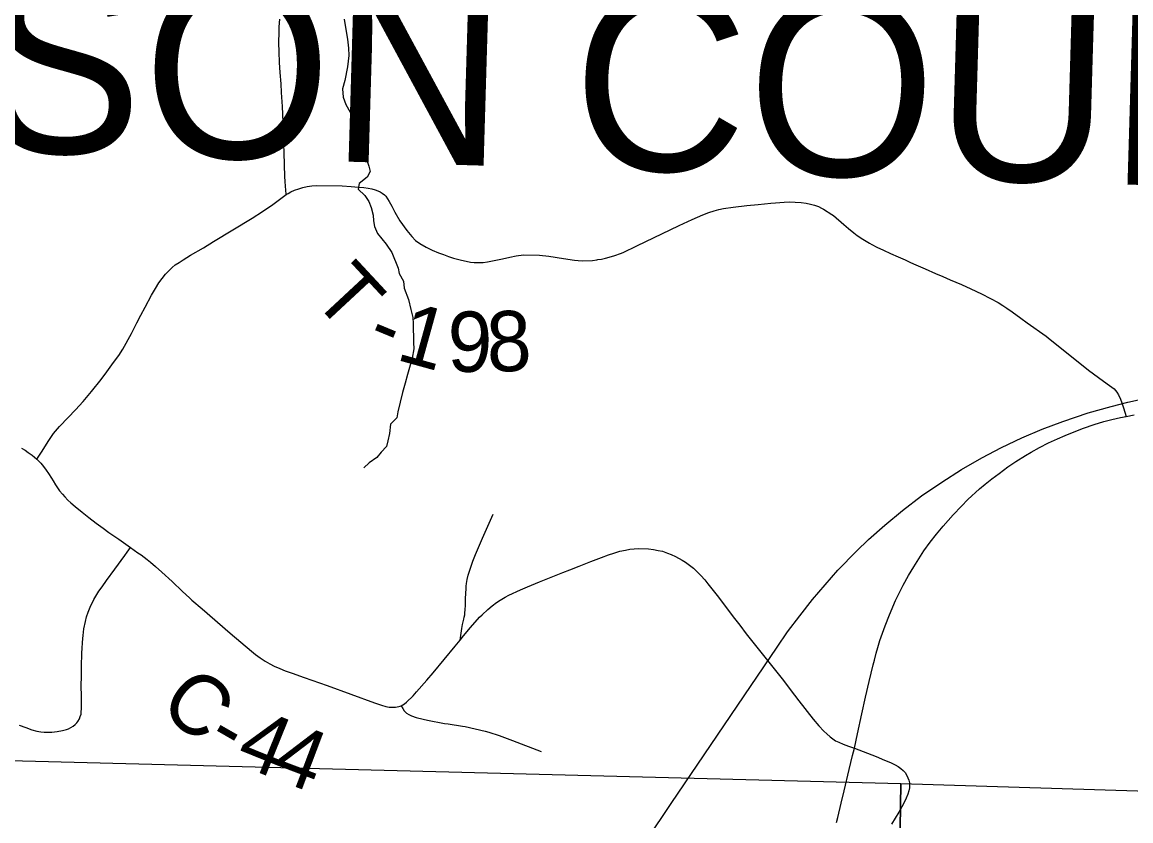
# Model space of a CAD drawing. Extents: x -19.9 to 41.9, y 0 to 32.3.
# Drawn here: x 3.184 to 4.229, y 16.837 to 17.59 of the extents above; entities that cross this region are included whole.
import ezdxf

# ---------------------------------------------------------------- set-up
doc = ezdxf.new("R2010")
doc.units = 0
for name, color, linetype in [('GM_X_Corporation', 7, 'Continuous'), ('GM_X_County_Road', 7, 'Continuous'), ('GM_X_County_Road_Text', 7, 'Continuous'), ('GM_X_County_Text', 7, 'Continuous'), ('GM_X_Minor_River', 7, 'Continuous'), ('GM_X_Rail_Line', 7, 'Continuous'), ('GM_X_State_Route', 7, 'Continuous'), ('GM_X_Township_Road', 7, 'Continuous'), ('GM_X_Township_Road_Text', 7, 'Continuous')]:
    doc.layers.add(name, color=color, linetype=linetype)

msp = doc.modelspace()

# ---------------------------------------------------------------- linework, layer by layer
at = {"layer": 'GM_X_Corporation'}
for points in [[(3.0015, 16.8981), (4.0122, 16.8721), (3.9969, 15.8607), (2.9854, 15.8784)], [(5.0159, 16.8409), (5.0026, 15.928), (5.0009, 15.8404), (3.9969, 15.8607), (4.0122, 16.8721)]]:
    msp.add_lwpolyline(points, close=True, dxfattribs=at)
at = {"layer": 'GM_X_County_Road'}
for points in [[(3.1832, 17.1883), (3.1868, 17.1862), (3.1897, 17.1842), (3.1935, 17.1815), (3.1955, 17.1798), (3.1977, 17.1777), (3.1994, 17.1762), (3.2014, 17.174), (3.204, 17.171), (3.2065, 17.1676), (3.2088, 17.1642), (3.2116, 17.1599), (3.2132, 17.1573), (3.2154, 17.1538), (3.2173, 17.1509), (3.2192, 17.1481), (3.222, 17.1448), (3.2241, 17.1424), (3.227, 17.1393), (3.2299, 17.1366), (3.2339, 17.1332), (3.2405, 17.1278), (3.2467, 17.1229), (3.2538, 17.1175), (3.2603, 17.1127), (3.2657, 17.1088), (3.2749, 17.1024), (3.2859, 17.0947), (3.2931, 17.0897), (3.296, 17.0877), (3.2988, 17.0855), (3.3018, 17.0832), (3.3049, 17.0807), (3.3096, 17.0766), (3.3155, 17.0713), (3.3253, 17.0625), (3.335, 17.0532), (3.3416, 17.0472), (3.3438, 17.0451), (3.3535, 17.0369), (3.3801, 17.014), (3.4, 16.9969), (3.4038, 16.9938), (3.4082, 16.9907), (3.413, 16.9876), (3.4174, 16.985), (3.4216, 16.9828), (3.4268, 16.9805), (3.4318, 16.9785), (3.4384, 16.9762), (3.4497, 16.9722), (3.4715, 16.9646), (3.5159, 16.9483), (3.5226, 16.946), (3.5268, 16.9448), (3.5299, 16.9442), (3.5323, 16.9441), (3.5358, 16.9442), (3.5388, 16.9447), (3.5403, 16.9451), (3.5413, 16.9455)], [(3.5413, 16.9455), (3.5427, 16.9462), (3.5444, 16.9474), (3.5461, 16.9487), (3.5523, 16.9548), (3.5557, 16.9585), (3.5653, 16.9694), (3.5713, 16.9766), (3.5919, 17.0017), (3.5966, 17.0073), (3.5998, 17.0112), (3.6066, 17.0191), (3.6151, 17.0288), (3.6174, 17.0312), (3.6228, 17.0361), (3.6268, 17.0396), (3.631, 17.0428), (3.6344, 17.045), (3.6391, 17.0477), (3.6427, 17.0496), (3.6535, 17.0547), (3.6602, 17.0576), (3.6714, 17.0621), (3.6841, 17.0672), (3.6936, 17.071), (3.7002, 17.0737), (3.7088, 17.0771), (3.7198, 17.0815), (3.7299, 17.0853), (3.7365, 17.0877), (3.7415, 17.0894), (3.7471, 17.091), (3.7525, 17.0922), (3.7566, 17.0929), (3.7608, 17.0934), (3.7647, 17.0936), (3.7743, 17.0933), (3.779, 17.0928), (3.7834, 17.0919), (3.7873, 17.091), (3.7922, 17.0894), (3.7957, 17.088), (3.7996, 17.0862), (3.8061, 17.0827), (3.8091, 17.0809), (3.8129, 17.0781), (3.8166, 17.075), (3.8198, 17.0719), (3.8235, 17.0681), (3.8272, 17.064), (3.8301, 17.0605), (3.8401, 17.0478), (3.8476, 17.0379), (3.8554, 17.0278), (3.8602, 17.0213), (3.8663, 17.0132), (3.9014, 16.9691), (3.9077, 16.9608), (3.9159, 16.9502), (3.9296, 16.9327), (3.9349, 16.9264), (3.9394, 16.9216), (3.9422, 16.9189), (3.9455, 16.916), (3.9479, 16.9143), (3.9506, 16.9125), (3.9535, 16.911), (3.9576, 16.9093), (3.9626, 16.9075), (3.9683, 16.9054)], [(3.5413, 16.9455), (3.5428, 16.9427), (3.544, 16.9408), (3.5448, 16.9398), (3.5461, 16.9386), (3.5483, 16.9372), (3.5509, 16.936), (3.5553, 16.9345), (3.5619, 16.9327), (3.566, 16.9318), (3.582, 16.9288), (3.5854, 16.9284), (3.5989, 16.9263), (3.6015, 16.9258), (3.6202, 16.9216), (3.6237, 16.9206), (3.6336, 16.9173), (3.6461, 16.9128), (3.6732, 16.9024)], [(3.9683, 16.9054), (3.9807, 16.9007), (3.9889, 16.8976), (3.9967, 16.8943), (4.0022, 16.8919), (4.0066, 16.8899), (4.0097, 16.8881), (4.0122, 16.8863), (4.0144, 16.8844), (4.016, 16.8825), (4.0174, 16.8804), (4.0188, 16.8776), (4.0195, 16.8752), (4.0201, 16.8729), (4.0201, 16.8715), (4.0201, 16.868), (4.0196, 16.8652), (4.0187, 16.8621), (4.017, 16.8583), (4.0151, 16.8543), (4.0129, 16.8501), (4.0101, 16.8452), (4.0034, 16.8338)]]:
    msp.add_lwpolyline(points, dxfattribs=at)
at = {"layer": 'GM_X_Minor_River'}
msp.add_lwpolyline([(3.4874, 17.5926), (3.4886, 17.5846), (3.4907, 17.5736), (3.4916, 17.5652), (3.4917, 17.5583), (3.4907, 17.5477), (3.4882, 17.5347), (3.486, 17.527), (3.4865, 17.519), (3.4889, 17.5122), (3.4932, 17.505), (3.4975, 17.496), (3.5026, 17.4831), (3.5061, 17.4729), (3.5082, 17.4619), (3.5106, 17.4539), (3.5118, 17.449), (3.5092, 17.4436), (3.5017, 17.4378), (3.5006, 17.4324), (3.5068, 17.4264), (3.5107, 17.4208), (3.513, 17.4151), (3.5146, 17.4079), (3.5151, 17.4025), (3.5159, 17.3972), (3.5187, 17.3904), (3.5271, 17.3806), (3.5322, 17.3727), (3.5384, 17.358), (3.5393, 17.353), (3.5432, 17.3455), (3.544, 17.339), (3.5479, 17.3284), (3.5504, 17.3189), (3.552, 17.3113), (3.5524, 17.3056), (3.5527, 17.2877), (3.5531, 17.282), (3.5514, 17.2732), (3.5489, 17.2644), (3.5471, 17.2576), (3.5449, 17.2495), (3.5424, 17.2407), (3.5381, 17.2224), (3.537, 17.2167), (3.5311, 17.2109), (3.5301, 17.2021), (3.5286, 17.1952), (3.5272, 17.1898), (3.5224, 17.1844), (3.5183, 17.1794), (3.5111, 17.1744), (3.5059, 17.1697)], dxfattribs=at)
at = {"layer": 'GM_X_Rail_Line'}
msp.add_lwpolyline([(3.7281, 16.7526), (3.7957, 16.8533), (3.8955, 17.0007), (3.9054, 17.0151), (3.9168, 17.0301), (3.9289, 17.0457), (3.9526, 17.0733), (3.9703, 17.0912), (3.9817, 17.1022), (3.9971, 17.1157), (4.0137, 17.1296), (4.0316, 17.1432), (4.0506, 17.1562), (4.0694, 17.1682), (4.0884, 17.179), (4.107, 17.1887), (4.1262, 17.1979), (4.1453, 17.206), (4.1648, 17.2134), (4.1887, 17.2214), (4.2102, 17.2275), (4.2259, 17.2316), (4.2444, 17.2356)], dxfattribs=at)
at = {"layer": 'GM_X_State_Route'}
msp.add_lwpolyline([(3.9513, 16.8354), (3.9526, 16.8402), (3.9559, 16.8536), (3.9587, 16.8653), (3.9635, 16.8855), (3.9666, 16.8984), (3.9683, 16.9054), (3.9712, 16.9189), (3.9752, 16.9377), (3.9789, 16.9536), (3.9822, 16.9682), (3.986, 16.9841), (3.9871, 16.9885), (3.9889, 16.995), (3.9904, 17.0003), (3.9924, 17.0069), (3.9947, 17.0137), (3.9973, 17.0209), (4.0013, 17.0311), (4.0071, 17.0446), (4.0143, 17.059), (4.0194, 17.0681), (4.0244, 17.0763), (4.0291, 17.084), (4.0339, 17.0916), (4.0397, 17.0996), (4.0458, 17.1073), (4.052, 17.1147), (4.0613, 17.1254), (4.0691, 17.1334), (4.0752, 17.1397), (4.0862, 17.1498), (4.0915, 17.1542), (4.0979, 17.1593), (4.1047, 17.1644), (4.1129, 17.1705), (4.1206, 17.1758), (4.1296, 17.1813), (4.1348, 17.1844), (4.1429, 17.1889), (4.1512, 17.1931), (4.1597, 17.1971), (4.1669, 17.2003), (4.1771, 17.2044), (4.1842, 17.207), (4.1943, 17.2104), (4.2034, 17.2132), (4.211, 17.2152), (4.2192, 17.2171), (4.2245, 17.2182), (4.2319, 17.2197)], dxfattribs=at)
at = {"layer": 'GM_X_Township_Road'}
for points in [[(3.4328, 17.4273), (3.4323, 17.4317), (3.4321, 17.4349), (3.4318, 17.4399), (3.4316, 17.4441), (3.4308, 17.4668), (3.4304, 17.4821), (3.4298, 17.4954), (3.4292, 17.5103), (3.4284, 17.5236), (3.4279, 17.5315), (3.4272, 17.5422), (3.4266, 17.5517), (3.4261, 17.5617), (3.4259, 17.5702), (3.4261, 17.5806), (3.4263, 17.5853), (3.4269, 17.5926)], [(3.1977, 17.1777), (3.1997, 17.1808), (3.2028, 17.1855), (3.2083, 17.1944), (3.2135, 17.2021), (3.219, 17.2086), (3.2272, 17.217), (3.2343, 17.2244), (3.2413, 17.2322), (3.2492, 17.2415), (3.2583, 17.253), (3.2638, 17.2601), (3.2699, 17.2689), (3.2749, 17.2755), (3.2789, 17.2814), (3.2869, 17.2964), (3.2921, 17.3064), (3.2959, 17.3137), (3.2998, 17.321), (3.3057, 17.3324), (3.3095, 17.3387), (3.3129, 17.344), (3.3159, 17.3482), (3.3191, 17.3522), (3.3221, 17.3555), (3.3254, 17.3586), (3.3283, 17.3609), (3.3318, 17.3633), (3.3356, 17.3656), (3.3426, 17.37), (3.3548, 17.3772), (3.3644, 17.3829), (3.4006, 17.4049), (3.4104, 17.4114), (3.4203, 17.418), (3.4328, 17.4273), (3.4345, 17.4283), (3.4373, 17.4298), (3.4407, 17.4313), (3.4447, 17.4328), (3.4486, 17.4339), (3.4526, 17.4347), (3.4569, 17.4354), (3.4612, 17.4357), (3.4856, 17.4355), (3.4939, 17.4348), (3.5009, 17.4342), (3.5061, 17.4338), (3.5102, 17.4332), (3.5134, 17.4326), (3.5166, 17.4318), (3.5191, 17.4308), (3.5214, 17.4297), (3.5233, 17.4285), (3.5253, 17.4269), (3.5267, 17.4256), (3.5299, 17.4208), (3.5323, 17.4163), (3.5353, 17.4108), (3.5399, 17.4025), (3.5465, 17.3933), (3.5513, 17.3877), (3.5548, 17.3839), (3.5587, 17.3811), (3.5648, 17.3776), (3.5703, 17.3748), (3.5764, 17.3724), (3.5812, 17.3707), (3.5858, 17.369), (3.5905, 17.3673), (3.5981, 17.3653), (3.6025, 17.3644), (3.6066, 17.3636), (3.6101, 17.3632), (3.614, 17.3631), (3.6185, 17.3633), (3.6225, 17.3638), (3.6289, 17.365), (3.6367, 17.3666), (3.6436, 17.3682), (3.6495, 17.3695), (3.6563, 17.3704), (3.6716, 17.3702), (3.6803, 17.3693), (3.6941, 17.3671), (3.7046, 17.3654), (3.7081, 17.3651), (3.7118, 17.3649), (3.7216, 17.3652), (3.7255, 17.3657), (3.7265, 17.3659), (3.73, 17.3665), (3.7338, 17.3674), (3.7371, 17.3682), (3.7425, 17.3698), (3.7479, 17.3718), (3.7505, 17.3728), (3.7631, 17.3789), (3.8032, 17.3981), (3.8154, 17.4038), (3.8254, 17.4081), (3.8311, 17.4103), (3.836, 17.412), (3.8404, 17.4132), (3.845, 17.4142), (3.8539, 17.4154), (3.8668, 17.4168), (3.8777, 17.418), (3.8896, 17.4191), (3.894, 17.4196), (3.902, 17.4202), (3.9068, 17.4204), (3.9126, 17.4202), (3.9181, 17.4197), (3.9228, 17.4191), (3.927, 17.4183), (3.9307, 17.4172), (3.9344, 17.4159), (3.9374, 17.4144), (3.9392, 17.4135), (3.9471, 17.4085), (3.9487, 17.4074), (3.9585, 17.3989), (3.9626, 17.3952), (3.9677, 17.3911), (3.971, 17.3886), (3.9763, 17.3852), (3.9824, 17.3815), (3.9846, 17.3801), (3.9894, 17.3778), (3.9957, 17.3748), (4.0022, 17.3718), (4.0095, 17.3686), (4.0161, 17.3656), (4.0205, 17.3636), (4.0239, 17.362), (4.0349, 17.3571), (4.0449, 17.3527), (4.0515, 17.3499), (4.0587, 17.347), (4.0691, 17.3425), (4.078, 17.3385), (4.0881, 17.3336), (4.0965, 17.3293), (4.1037, 17.3254), (4.1083, 17.3226), (4.1119, 17.3202), (4.1169, 17.3166), (4.1251, 17.3106), (4.1312, 17.3065), (4.1491, 17.2937), (4.1528, 17.2908), (4.1792, 17.2695), (4.1891, 17.2617), (4.1985, 17.2547), (4.2065, 17.2489), (4.2108, 17.2458), (4.213, 17.244), (4.2155, 17.241), (4.2171, 17.2386), (4.2191, 17.2344), (4.2204, 17.2309), (4.222, 17.2261), (4.2245, 17.2182)], [(3.5966, 17.0073), (3.5982, 17.0181), (3.5989, 17.022), (3.6002, 17.0272), (3.6006, 17.0288), (3.601, 17.031), (3.6013, 17.0328), (3.6015, 17.0362), (3.6017, 17.0399), (3.6019, 17.0466), (3.6021, 17.0511), (3.6024, 17.0558), (3.6025, 17.058), (3.6028, 17.0608), (3.6034, 17.0643), (3.6043, 17.0686), (3.6088, 17.0818), (3.6112, 17.0879), (3.6179, 17.1034), (3.6215, 17.112), (3.6277, 17.126)], [(3.1811, 16.927), (3.1873, 16.9249), (3.1931, 16.9228), (3.1978, 16.9215), (3.2016, 16.9208), (3.2048, 16.9206), (3.2081, 16.9205), (3.2119, 16.9206), (3.2168, 16.9212), (3.2219, 16.9221), (3.2258, 16.9231), (3.2276, 16.9238), (3.2299, 16.9249), (3.2319, 16.9262), (3.2339, 16.9277), (3.2355, 16.9294), (3.2365, 16.9307), (3.2379, 16.9332), (3.2387, 16.9352), (3.2394, 16.9376), (3.2397, 16.9399), (3.2399, 16.9422), (3.2398, 16.9528), (3.2397, 16.9657), (3.2398, 16.9717), (3.2399, 16.9825), (3.2403, 16.9951), (3.2404, 16.9998), (3.2407, 17.0048), (3.241, 17.0087), (3.2413, 17.0118), (3.2422, 17.0178), (3.2436, 17.0248), (3.2447, 17.0291), (3.2461, 17.0337), (3.2479, 17.0384), (3.2516, 17.0457), (3.2563, 17.0534), (3.2592, 17.0574), (3.2634, 17.0634), (3.2714, 17.0742), (3.2806, 17.0869), (3.283, 17.0903), (3.2859, 17.0947)]]:
    msp.add_lwpolyline(points, dxfattribs=at)

# ---------------------------------------------------------------- texts
at = {"layer": 'GM_X_County_Road_Text'}
for s, rotation, p in [('C', 320.8111, (3.311, 16.9424)), ('-', 330.1136, (3.3554, 16.9072)), ('4', 338.0023, (3.3833, 16.8919)), ('4', 339.2912, (3.4171, 16.8782))]:
    msp.add_text(s, height=0.0568, rotation=rotation, dxfattribs=at).set_placement(p)
at = {"layer": 'GM_X_County_Text'}
msp.add_text('HARRISON COUNTY', height=0.170455, rotation=358.3166, dxfattribs=at).set_placement((2.4348, 17.4893))
at = {"layer": 'GM_X_Township_Road_Text'}
for s, rotation, p in [('T', 312.9085, (3.4557, 17.3296)), ('1', 344.5113, (3.535, 17.272)), ('9', 359.3184, (3.5845, 17.2604)), ('8', 2.1213, (3.6226, 17.26)), ('-', 337.4934, (3.5063, 17.2834))]:
    msp.add_text(s, height=0.0568, rotation=rotation, dxfattribs=at).set_placement(p)

doc.saveas('drawing.dxf')
